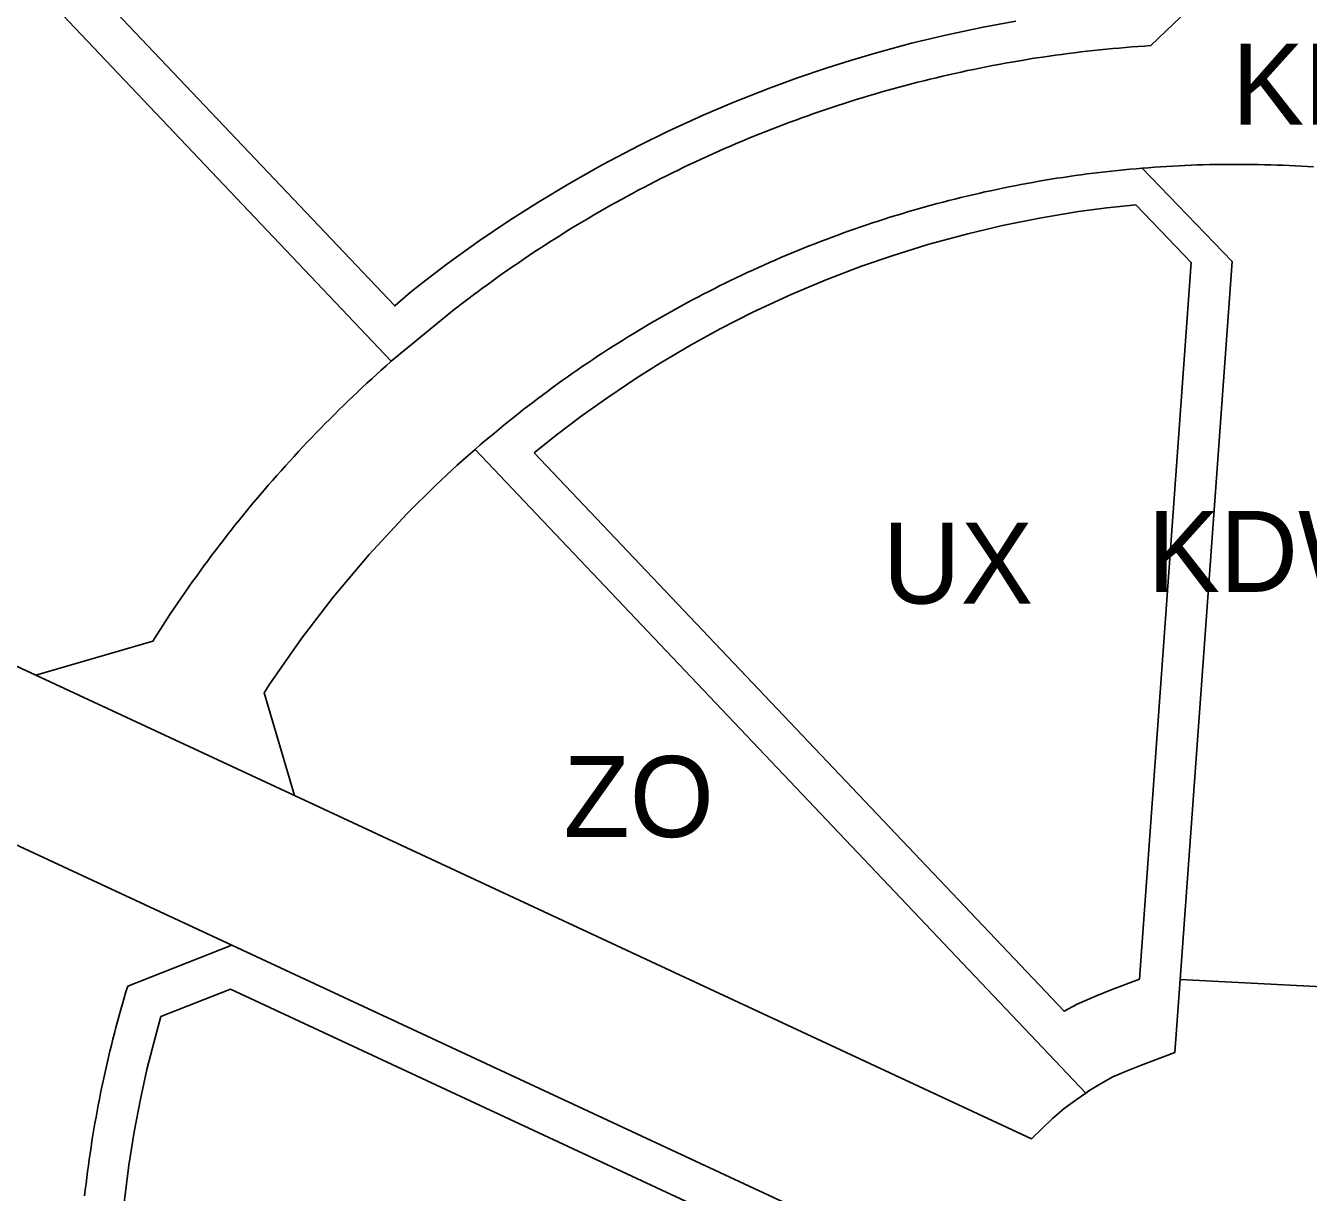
# Model space of a CAD drawing. Extents: x -297746 to -295403, y 27112 to 28877.
# Drawn here: x -297178.2 to -297020, y 27745.5 to 27889.5 of the extents above; entities that cross this region are included whole.
import ezdxf

# ---------------------------------------------------------------- set-up
doc = ezdxf.new("R2010")
doc.units = 0
for name, color, linetype in [('linie_rozgraniczajace', 7, 'Continuous'), ('linie_zabudowy_nieprzekraczalne', 7, 'Continuous'), ('linie_zabudowy_obowiazujace', 7, 'Continuous'), ('oznaczenia_przeznaczen', 7, 'Continuous')]:
    doc.layers.add(name, color=color, linetype=linetype)

msp = doc.modelspace()

# ---------------------------------------------------------------- linework, layer by layer
at = {"layer": 'linie_rozgraniczajace'}
for points in [[(-297348.943, 28075.477), (-297133.128, 27848.059), (-297133.18, 27848.017), (-297133.776, 27847.489), (-297134.37, 27846.958), (-297134.961, 27846.424), (-297135.549, 27845.888), (-297136.135, 27845.348), (-297136.718, 27844.805), (-297137.298, 27844.26), (-297137.876, 27843.711), (-297138.45, 27843.16), (-297139.022, 27842.606), (-297139.592, 27842.049), (-297140.158, 27841.489), (-297140.721, 27840.926), (-297141.282, 27840.361), (-297141.84, 27839.792), (-297142.395, 27839.221), (-297142.947, 27838.647), (-297143.496, 27838.07), (-297144.043, 27837.491), (-297144.586, 27836.909), (-297145.127, 27836.324), (-297145.664, 27835.736), (-297146.199, 27835.146), (-297146.73, 27834.553), (-297147.259, 27833.957), (-297147.785, 27833.359), (-297148.307, 27832.758), (-297148.827, 27832.154), (-297149.343, 27831.548), (-297149.857, 27830.939), (-297150.367, 27830.328), (-297150.875, 27829.714), (-297151.379, 27829.098), (-297151.88, 27828.479), (-297152.378, 27827.857), (-297152.873, 27827.233), (-297153.365, 27826.607), (-297153.854, 27825.978), (-297154.339, 27825.347), (-297154.821, 27824.713), (-297155.301, 27824.077), (-297155.776, 27823.438), (-297156.249, 27822.797), (-297156.719, 27822.154), (-297157.185, 27821.508), (-297157.648, 27820.86), (-297158.108, 27820.21), (-297158.564, 27819.557), (-297159.017, 27818.902), (-297159.467, 27818.245), (-297159.914, 27817.586), (-297160.357, 27816.924), (-297160.73, 27816.36), (-297162.545, 27813.525), (-297177, 27809.324), (-297402.243, 27914.223)], [(-297133.128, 27848.059), (-297348.943, 28075.477)], [(-297402.243, 27914.223), (-297177, 27809.324), (-297145.09, 27794.463), (-297054.137, 27752.105), (-297051.53, 27754.599), (-297050.097, 27755.853), (-297048.619, 27756.928), (-297047.424, 27757.747), (-297047.051, 27758.003), (-297045.618, 27758.899), (-297044.095, 27759.75), (-297042.528, 27760.422), (-297040.691, 27761.138), (-297036.451, 27762.747), (-297035.795, 27771.765), (-297015.819, 27770.719), (-297016.52, 27761.077), (-297013.371, 27759.66), (-297011.669, 27758.72), (-297009.698, 27757.466), (-297007.727, 27756.032), (-297005.622, 27754.196), (-297003.607, 27752.36), (-297002.218, 27750.658)], [(-297026.524, 27899.372), (-297039.392, 27887.009), (-297040.179, 27886.958), (-297040.965, 27886.903), (-297041.751, 27886.844), (-297042.537, 27886.781), (-297043.323, 27886.714), (-297044.108, 27886.644), (-297044.893, 27886.569), (-297045.678, 27886.49), (-297046.462, 27886.407), (-297047.246, 27886.321), (-297048.029, 27886.23), (-297048.812, 27886.135), (-297049.594, 27886.037), (-297050.376, 27885.934), (-297051.157, 27885.827), (-297051.938, 27885.717), (-297052.718, 27885.602), (-297053.498, 27885.484), (-297054.277, 27885.362), (-297055.055, 27885.235), (-297055.833, 27885.105), (-297056.61, 27884.971), (-297057.386, 27884.832), (-297058.162, 27884.69), (-297058.937, 27884.544), (-297059.711, 27884.394), (-297060.484, 27884.24), (-297061.257, 27884.083), (-297062.028, 27883.921), (-297062.799, 27883.755), (-297063.569, 27883.586), (-297064.338, 27883.412), (-297065.107, 27883.235), (-297065.874, 27883.054), (-297066.641, 27882.868), (-297067.406, 27882.679), (-297068.171, 27882.486), (-297068.934, 27882.29), (-297069.697, 27882.089), (-297070.458, 27881.885), (-297071.219, 27881.676), (-297071.978, 27881.464), (-297072.737, 27881.248), (-297073.494, 27881.028), (-297074.25, 27880.804), (-297075.005, 27880.576)], [(-297052.718, 27885.602), (-297051.938, 27885.717), (-297051.157, 27885.827), (-297050.376, 27885.934), (-297049.594, 27886.037), (-297048.812, 27886.135), (-297048.029, 27886.23), (-297047.246, 27886.321), (-297046.462, 27886.407), (-297045.678, 27886.49), (-297044.893, 27886.569), (-297044.108, 27886.644), (-297043.323, 27886.714), (-297042.537, 27886.781), (-297041.751, 27886.844), (-297040.965, 27886.903), (-297040.179, 27886.958), (-297039.392, 27887.009), (-297026.524, 27899.372)], [(-297125.389, 27854.431), (-297122.668, 27856.484), (-297122.625, 27856.516), (-297121.992, 27856.986), (-297121.356, 27857.452), (-297120.717, 27857.915), (-297120.077, 27858.375), (-297119.434, 27858.831), (-297118.789, 27859.285), (-297118.141, 27859.735), (-297117.491, 27860.181), (-297116.839, 27860.625), (-297116.185, 27861.065), (-297115.529, 27861.502), (-297114.87, 27861.935), (-297114.209, 27862.365), (-297113.546, 27862.792), (-297112.881, 27863.215), (-297112.213, 27863.635), (-297111.544, 27864.052), (-297110.872, 27864.465), (-297110.199, 27864.875), (-297109.523, 27865.281), (-297108.845, 27865.684), (-297108.165, 27866.083), (-297107.483, 27866.48), (-297106.8, 27866.872), (-297106.114, 27867.261), (-297105.426, 27867.647), (-297104.736, 27868.029), (-297104.045, 27868.407), (-297103.351, 27868.782), (-297102.655, 27869.154), (-297101.958, 27869.522), (-297101.259, 27869.887), (-297100.558, 27870.247), (-297099.855, 27870.605), (-297099.15, 27870.959), (-297098.444, 27871.309), (-297097.736, 27871.656), (-297097.026, 27871.999), (-297096.314, 27872.338), (-297095.6, 27872.674), (-297094.885, 27873.006), (-297094.169, 27873.335), (-297093.45, 27873.659), (-297092.73, 27873.981), (-297092.008, 27874.298), (-297091.285, 27874.612), (-297090.56, 27874.923), (-297089.834, 27875.229), (-297089.106, 27875.532), (-297088.376, 27875.831), (-297087.645, 27876.127), (-297086.912, 27876.419), (-297086.178, 27876.707), (-297085.443, 27876.991), (-297084.706, 27877.272), (-297083.968, 27877.548), (-297083.228, 27877.822), (-297082.487, 27878.091), (-297081.745, 27878.356), (-297081.001, 27878.618), (-297080.256, 27878.876), (-297079.509, 27879.131), (-297078.762, 27879.381), (-297078.013, 27879.628), (-297077.263, 27879.871), (-297076.511, 27880.11), (-297075.759, 27880.345), (-297075.005, 27880.576), (-297074.25, 27880.804), (-297073.494, 27881.028), (-297072.737, 27881.248), (-297071.978, 27881.464), (-297071.219, 27881.676), (-297070.458, 27881.885), (-297069.697, 27882.089), (-297068.934, 27882.29), (-297068.171, 27882.486), (-297067.406, 27882.679), (-297066.641, 27882.868), (-297065.874, 27883.054), (-297065.107, 27883.235), (-297064.338, 27883.412), (-297063.569, 27883.586), (-297062.799, 27883.755), (-297062.028, 27883.921), (-297061.257, 27884.083), (-297060.484, 27884.24), (-297059.711, 27884.394), (-297058.937, 27884.544), (-297058.162, 27884.69), (-297057.386, 27884.832), (-297056.61, 27884.971), (-297055.833, 27885.105), (-297055.055, 27885.235), (-297054.277, 27885.362), (-297053.498, 27885.484), (-297052.718, 27885.602)], [(-297075.005, 27880.576), (-297075.759, 27880.345), (-297076.511, 27880.11), (-297077.263, 27879.871), (-297078.013, 27879.628), (-297078.762, 27879.381), (-297079.509, 27879.131), (-297080.256, 27878.876), (-297081.001, 27878.618), (-297081.745, 27878.356), (-297082.487, 27878.091), (-297083.228, 27877.822), (-297083.968, 27877.548), (-297084.706, 27877.272), (-297085.443, 27876.991), (-297086.178, 27876.707), (-297086.912, 27876.419), (-297087.645, 27876.127), (-297088.376, 27875.831), (-297089.106, 27875.532), (-297089.834, 27875.229), (-297090.56, 27874.923), (-297091.285, 27874.612), (-297092.008, 27874.298), (-297092.73, 27873.981), (-297093.45, 27873.659), (-297094.169, 27873.335), (-297094.885, 27873.006), (-297095.6, 27872.674), (-297096.314, 27872.338), (-297097.026, 27871.999), (-297097.736, 27871.656), (-297098.444, 27871.309), (-297099.15, 27870.959), (-297099.855, 27870.605), (-297100.558, 27870.247), (-297101.259, 27869.887), (-297101.958, 27869.522), (-297102.655, 27869.154), (-297103.351, 27868.782), (-297104.045, 27868.407), (-297104.736, 27868.029), (-297105.426, 27867.647), (-297106.114, 27867.261), (-297106.8, 27866.872), (-297107.483, 27866.48), (-297108.165, 27866.083), (-297108.845, 27865.684), (-297109.523, 27865.281), (-297110.199, 27864.875), (-297110.872, 27864.465), (-297111.544, 27864.052), (-297112.213, 27863.635), (-297112.881, 27863.215), (-297113.546, 27862.792), (-297114.209, 27862.365), (-297114.87, 27861.935), (-297115.529, 27861.502), (-297116.185, 27861.065), (-297116.839, 27860.625), (-297117.491, 27860.181), (-297118.141, 27859.735), (-297118.789, 27859.285), (-297119.434, 27858.831), (-297120.077, 27858.375), (-297120.717, 27857.915), (-297121.356, 27857.452), (-297121.992, 27856.986), (-297122.625, 27856.516), (-297122.668, 27856.484), (-297125.389, 27854.431), (-297133.128, 27848.059)], [(-297033.681, 27872.279), (-297034.437, 27872.252), (-297035.193, 27872.22), (-297035.948, 27872.185), (-297036.703, 27872.145), (-297037.458, 27872.101), (-297038.213, 27872.054), (-297038.968, 27872.002), (-297039.722, 27871.947), (-297040.476, 27871.887), (-297041.229, 27871.824), (-297041.983, 27871.756), (-297042.736, 27871.685), (-297043.488, 27871.609), (-297044.24, 27871.53), (-297044.992, 27871.446), (-297045.743, 27871.359), (-297046.494, 27871.267), (-297047.244, 27871.172), (-297047.994, 27871.073), (-297048.743, 27870.969), (-297049.492, 27870.862), (-297050.24, 27870.751), (-297050.988, 27870.636), (-297051.734, 27870.517), (-297052.481, 27870.394), (-297053.226, 27870.267), (-297053.971, 27870.136), (-297054.715, 27870.001), (-297055.459, 27869.862), (-297056.201, 27869.719), (-297056.943, 27869.573), (-297057.685, 27869.422), (-297058.425, 27869.267), (-297059.164, 27869.109), (-297059.903, 27868.947), (-297060.641, 27868.78), (-297061.378, 27868.61), (-297062.114, 27868.436), (-297062.849, 27868.258), (-297063.583, 27868.077), (-297064.316, 27867.891), (-297065.048, 27867.701), (-297065.78, 27867.508), (-297066.51, 27867.311), (-297067.239, 27867.109), (-297067.967, 27866.904), (-297068.694, 27866.696), (-297069.419, 27866.483), (-297070.144, 27866.266), (-297070.867, 27866.046), (-297071.59, 27865.822), (-297072.311, 27865.594), (-297073.031, 27865.362), (-297073.749, 27865.126), (-297074.467, 27864.887), (-297075.183, 27864.644), (-297075.898, 27864.397), (-297076.611, 27864.146), (-297077.324, 27863.891), (-297078.034, 27863.633), (-297078.744, 27863.371), (-297079.452, 27863.105), (-297080.159, 27862.836), (-297080.864, 27862.562), (-297081.568, 27862.285), (-297082.27, 27862.005), (-297082.971, 27861.72), (-297083.67, 27861.432), (-297084.368, 27861.14), (-297085.064, 27860.845), (-297085.758, 27860.545), (-297086.451, 27860.243), (-297087.143, 27859.936), (-297087.833, 27859.626), (-297088.521, 27859.312), (-297089.207, 27858.995), (-297089.892, 27858.674), (-297090.575, 27858.349), (-297091.256, 27858.02), (-297091.936, 27857.689), (-297092.614, 27857.353), (-297093.29, 27857.014), (-297093.964, 27856.671), (-297094.636, 27856.325), (-297095.307, 27855.975), (-297095.976, 27855.622), (-297096.642, 27855.265), (-297097.307, 27854.905), (-297097.97, 27854.541), (-297098.632, 27854.174), (-297099.291, 27853.803), (-297099.948, 27853.428), (-297100.603, 27853.051), (-297101.256, 27852.669), (-297101.907, 27852.285), (-297102.556, 27851.896), (-297103.203, 27851.505), (-297103.848, 27851.11), (-297104.491, 27850.711)], [(-297015.819, 27770.719), (-297035.795, 27771.765), (-297029.356, 27860.362), (-297040.476, 27871.887), (-297039.722, 27871.947), (-297038.968, 27872.002), (-297038.213, 27872.054), (-297037.458, 27872.101), (-297036.703, 27872.145), (-297035.948, 27872.185), (-297035.193, 27872.22), (-297034.437, 27872.252), (-297033.681, 27872.279), (-297032.925, 27872.303), (-297032.169, 27872.323), (-297031.413, 27872.338), (-297030.657, 27872.35), (-297029.9, 27872.357), (-297029.144, 27872.361), (-297028.388, 27872.361), (-297027.632, 27872.356), (-297026.875, 27872.348), (-297026.119, 27872.335), (-297025.363, 27872.319), (-297024.607, 27872.299), (-297023.851, 27872.274), (-297023.095, 27872.246), (-297022.34, 27872.214), (-297021.584, 27872.177), (-297020.829, 27872.137), (-297020.074, 27872.092), (-297019.319, 27872.044)], [(-297019.319, 27872.044), (-297020.074, 27872.092), (-297020.829, 27872.137), (-297021.584, 27872.177), (-297022.34, 27872.214), (-297023.095, 27872.246), (-297023.851, 27872.274), (-297024.607, 27872.299), (-297025.363, 27872.319), (-297026.119, 27872.335), (-297026.875, 27872.348), (-297027.632, 27872.356), (-297028.388, 27872.361), (-297029.144, 27872.361), (-297029.9, 27872.357), (-297030.657, 27872.35), (-297031.413, 27872.338), (-297032.169, 27872.323), (-297032.925, 27872.303), (-297033.681, 27872.279)], [(-297057.685, 27869.422), (-297056.943, 27869.573), (-297056.201, 27869.719), (-297055.459, 27869.862), (-297054.715, 27870.001), (-297053.971, 27870.136), (-297053.226, 27870.267), (-297052.481, 27870.394), (-297051.734, 27870.517), (-297050.988, 27870.636), (-297050.24, 27870.751), (-297049.492, 27870.862), (-297048.743, 27870.969), (-297047.994, 27871.073), (-297047.244, 27871.172), (-297046.494, 27871.267), (-297045.743, 27871.359), (-297044.992, 27871.446), (-297044.24, 27871.53), (-297043.488, 27871.609), (-297042.736, 27871.685), (-297041.983, 27871.756), (-297041.229, 27871.824), (-297040.476, 27871.887), (-297029.356, 27860.362), (-297035.795, 27771.765), (-297036.451, 27762.747), (-297040.691, 27761.138), (-297042.528, 27760.422), (-297044.095, 27759.75), (-297045.618, 27758.899), (-297047.051, 27758.003), (-297047.424, 27757.747)], [(-297047.424, 27757.747), (-297122.792, 27837.167), (-297122.714, 27837.234), (-297122.143, 27837.729), (-297121.568, 27838.221), (-297120.991, 27838.71), (-297120.411, 27839.196), (-297119.829, 27839.679), (-297119.245, 27840.158), (-297118.657, 27840.635), (-297118.068, 27841.108), (-297117.475, 27841.579), (-297116.881, 27842.046), (-297116.283, 27842.51), (-297115.684, 27842.971), (-297115.082, 27843.429), (-297114.477, 27843.883), (-297113.87, 27844.334), (-297113.261, 27844.783), (-297112.649, 27845.227), (-297112.035, 27845.669), (-297111.419, 27846.107), (-297110.801, 27846.543), (-297110.18, 27846.974), (-297109.556, 27847.403), (-297108.931, 27847.828), (-297108.303, 27848.25), (-297107.673, 27848.669), (-297107.041, 27849.084), (-297106.407, 27849.496), (-297105.771, 27849.904), (-297105.132, 27850.31), (-297104.491, 27850.711), (-297103.848, 27851.11), (-297103.203, 27851.505), (-297102.556, 27851.896), (-297101.907, 27852.285), (-297101.256, 27852.669), (-297100.603, 27853.051), (-297099.948, 27853.428), (-297099.291, 27853.803), (-297098.632, 27854.174), (-297097.97, 27854.541), (-297097.307, 27854.905), (-297096.642, 27855.265), (-297095.976, 27855.622), (-297095.307, 27855.975), (-297094.636, 27856.325), (-297093.964, 27856.671), (-297093.29, 27857.014), (-297092.614, 27857.353), (-297091.936, 27857.689), (-297091.256, 27858.02), (-297090.575, 27858.349), (-297089.892, 27858.674), (-297089.207, 27858.995), (-297088.521, 27859.312), (-297087.833, 27859.626), (-297087.143, 27859.936), (-297086.451, 27860.243), (-297085.758, 27860.545), (-297085.064, 27860.845), (-297084.368, 27861.14), (-297083.67, 27861.432), (-297082.971, 27861.72), (-297082.27, 27862.005), (-297081.568, 27862.285), (-297080.864, 27862.562), (-297080.159, 27862.836), (-297079.452, 27863.105), (-297078.744, 27863.371), (-297078.034, 27863.633), (-297077.324, 27863.891), (-297076.611, 27864.146), (-297075.898, 27864.397), (-297075.183, 27864.644), (-297074.467, 27864.887), (-297073.749, 27865.126), (-297073.031, 27865.362), (-297072.311, 27865.594), (-297071.59, 27865.822), (-297070.867, 27866.046), (-297070.144, 27866.266), (-297069.419, 27866.483), (-297068.694, 27866.696), (-297067.967, 27866.904), (-297067.239, 27867.109), (-297066.51, 27867.311), (-297065.78, 27867.508), (-297065.048, 27867.701), (-297064.316, 27867.891), (-297063.583, 27868.077), (-297062.849, 27868.258), (-297062.114, 27868.436), (-297061.378, 27868.61), (-297060.641, 27868.78), (-297059.903, 27868.947), (-297059.164, 27869.109), (-297058.425, 27869.267), (-297057.685, 27869.422)], [(-297104.491, 27850.711), (-297105.132, 27850.31), (-297105.771, 27849.904), (-297106.407, 27849.496), (-297107.041, 27849.084), (-297107.673, 27848.669), (-297108.303, 27848.25), (-297108.931, 27847.828), (-297109.556, 27847.403), (-297110.18, 27846.974), (-297110.801, 27846.543), (-297111.419, 27846.107), (-297112.035, 27845.669), (-297112.649, 27845.227), (-297113.261, 27844.783), (-297113.87, 27844.334), (-297114.477, 27843.883), (-297115.082, 27843.429), (-297115.684, 27842.971), (-297116.283, 27842.51), (-297116.881, 27842.046), (-297117.475, 27841.579), (-297118.068, 27841.108), (-297118.657, 27840.635), (-297119.245, 27840.158), (-297119.829, 27839.679), (-297120.411, 27839.196), (-297120.991, 27838.71), (-297121.568, 27838.221), (-297122.143, 27837.729), (-297122.714, 27837.234), (-297122.792, 27837.167), (-297123.635, 27836.426), (-297124.984, 27835.217), (-297127.654, 27832.729), (-297131.16, 27829.259), (-297135.859, 27824.208), (-297140.291, 27818.959), (-297144.215, 27813.845), (-297148.1, 27808.266), (-297148.813, 27807.138), (-297145.09, 27794.463), (-297177, 27809.324), (-297162.545, 27813.525), (-297160.73, 27816.36), (-297160.357, 27816.924), (-297159.914, 27817.586), (-297159.467, 27818.245), (-297159.017, 27818.902), (-297158.564, 27819.557), (-297158.108, 27820.21), (-297157.648, 27820.86), (-297157.185, 27821.508), (-297156.719, 27822.154), (-297156.249, 27822.797), (-297155.776, 27823.438), (-297155.301, 27824.077), (-297154.821, 27824.713), (-297154.339, 27825.347), (-297153.854, 27825.978), (-297153.365, 27826.607), (-297152.873, 27827.233), (-297152.378, 27827.857), (-297151.88, 27828.479), (-297151.379, 27829.098), (-297150.875, 27829.714), (-297150.367, 27830.328), (-297149.857, 27830.939), (-297149.343, 27831.548), (-297148.827, 27832.154), (-297148.307, 27832.758), (-297147.785, 27833.359), (-297147.259, 27833.957), (-297146.73, 27834.553), (-297146.199, 27835.146), (-297145.664, 27835.736), (-297145.127, 27836.324), (-297144.586, 27836.909), (-297144.043, 27837.491), (-297143.496, 27838.07), (-297142.947, 27838.647), (-297142.395, 27839.221), (-297141.84, 27839.792), (-297141.282, 27840.361), (-297140.721, 27840.926), (-297140.158, 27841.489), (-297139.592, 27842.049), (-297139.022, 27842.606), (-297138.45, 27843.16), (-297137.876, 27843.711), (-297137.298, 27844.26), (-297136.718, 27844.805), (-297136.135, 27845.348), (-297135.549, 27845.888), (-297134.961, 27846.424), (-297134.37, 27846.958), (-297133.776, 27847.489), (-297133.18, 27848.017), (-297133.128, 27848.059), (-297125.389, 27854.431)], [(-297181.991, 27789.586), (-297152.791, 27775.987), (-297165.659, 27770.949), (-297165.877, 27770.224), (-297166.091, 27769.499), (-297166.302, 27768.773), (-297166.508, 27768.045), (-297166.711, 27767.316)], [(-297062.466, 27733.921), (-297152.791, 27775.987), (-297181.991, 27789.586)], [(-297170.976, 27745.056), (-297170.891, 27745.807), (-297170.802, 27746.559), (-297170.709, 27747.309), (-297170.612, 27748.059), (-297170.511, 27748.809), (-297170.406, 27749.558), (-297170.298, 27750.306), (-297170.185, 27751.054), (-297170.068, 27751.801), (-297169.947, 27752.548), (-297169.823, 27753.294), (-297169.694, 27754.039), (-297169.562, 27754.784), (-297169.425, 27755.528), (-297169.285, 27756.271), (-297169.141, 27757.013), (-297168.993, 27757.755), (-297168.84, 27758.496), (-297168.684, 27759.236), (-297168.524, 27759.975), (-297168.361, 27760.713), (-297168.193, 27761.451), (-297168.021, 27762.187), (-297167.846, 27762.923), (-297167.666, 27763.658), (-297167.483, 27764.391), (-297167.296, 27765.124), (-297167.104, 27765.856), (-297166.91, 27766.587), (-297166.711, 27767.316), (-297166.508, 27768.045), (-297166.302, 27768.773), (-297166.091, 27769.499), (-297165.877, 27770.224), (-297165.659, 27770.949), (-297152.791, 27775.987), (-297062.466, 27733.921)], [(-297166.711, 27767.316), (-297166.91, 27766.587), (-297167.104, 27765.856), (-297167.296, 27765.124), (-297167.483, 27764.391), (-297167.666, 27763.658), (-297167.846, 27762.923), (-297168.021, 27762.187), (-297168.193, 27761.451), (-297168.361, 27760.713), (-297168.524, 27759.975), (-297168.684, 27759.236), (-297168.84, 27758.496), (-297168.993, 27757.755), (-297169.141, 27757.013), (-297169.285, 27756.271), (-297169.425, 27755.528), (-297169.562, 27754.784), (-297169.694, 27754.039), (-297169.823, 27753.294), (-297169.947, 27752.548), (-297170.068, 27751.801), (-297170.185, 27751.054), (-297170.298, 27750.306), (-297170.406, 27749.558), (-297170.511, 27748.809), (-297170.612, 27748.059), (-297170.709, 27747.309), (-297170.802, 27746.559), (-297170.891, 27745.807), (-297170.976, 27745.056)]]:
    msp.add_lwpolyline(points, dxfattribs=at)
msp.add_lwpolyline([(-297054.137, 27752.105), (-297145.09, 27794.463), (-297148.813, 27807.138), (-297148.1, 27808.266), (-297144.215, 27813.845), (-297140.291, 27818.959), (-297135.859, 27824.208), (-297131.16, 27829.259), (-297127.654, 27832.729), (-297124.984, 27835.217), (-297123.635, 27836.426), (-297122.792, 27837.167), (-297047.424, 27757.747), (-297048.619, 27756.928), (-297050.097, 27755.853), (-297051.53, 27754.599)], close=True, dxfattribs=at)
at = {"layer": 'linie_zabudowy_nieprzekraczalne'}
msp.add_lwpolyline([(-297167.124, 27891.151), (-297132.706, 27854.883), (-297130.751, 27856.583), (-297128.876, 27858.055), (-297126.216, 27860.069), (-297122.275, 27862.902), (-297118.615, 27865.378), (-297115.062, 27867.649), (-297111.233, 27869.956), (-297107.038, 27872.325), (-297102.54, 27874.688), (-297099.041, 27876.407), (-297094.665, 27878.414), (-297090.856, 27880.037), (-297086.468, 27881.769), (-297083.006, 27883.033), (-297079.359, 27884.272), (-297076.475, 27885.185), (-297073.265, 27886.132), (-297068.916, 27887.304), (-297064.523, 27888.359), (-297060.104, 27889.293), (-297056.078, 27890.034)], dxfattribs=at)
at = {"layer": 'linie_zabudowy_obowiazujace'}
for points in [[(-297115.503, 27836.755), (-297050.109, 27767.845), (-297048.513, 27768.737), (-297046.313, 27769.68), (-297044.279, 27770.473), (-297040.807, 27771.79), (-297034.408, 27860.259), (-297038.279, 27864.279), (-297041.265, 27867.38), (-297044.825, 27866.997), (-297048.343, 27866.525), (-297053.128, 27865.733), (-297057.704, 27864.811), (-297062.004, 27863.797), (-297066.925, 27862.454), (-297071.339, 27861.079), (-297075.108, 27859.774), (-297079.581, 27858.064), (-297083.797, 27856.285), (-297088.497, 27854.102), (-297092.534, 27852.049), (-297096.136, 27850.074), (-297099.948, 27847.826), (-297102.848, 27846.002), (-297106.55, 27843.522), (-297109.588, 27841.354), (-297112.767, 27838.947), (-297115.503, 27836.755)], [(-297073.258, 27733.435), (-297152.959, 27770.553), (-297161.552, 27767.188), (-297162.41, 27764.111), (-297163.278, 27760.652), (-297164.091, 27756.982), (-297164.853, 27752.978), (-297165.505, 27748.842), (-297166.04, 27744.544), (-297166.418, 27740.433), (-297166.671, 27736.179), (-297166.78, 27732.429), (-297166.778, 27728.538), (-297166.686, 27725.194), (-297166.563, 27722.113), (-297166.388, 27718.856), (-297166.307, 27717.62), (-297157.809, 27711.947), (-297073.258, 27733.435)]]:
    msp.add_lwpolyline(points, dxfattribs=at)

# ---------------------------------------------------------------- texts
at = {"layer": 'oznaczenia_przeznaczen'}
for s, p in [('KD/D', (-297029.417, 27877.268)), ('KDW/D', (-297039.811, 27819.599)), ('UX', (-297072.513, 27818.158)), ('ZO', (-297111.882, 27789.342))]:
    msp.add_text(s, height=10, dxfattribs=at).set_placement(p)

doc.saveas('drawing.dxf')
